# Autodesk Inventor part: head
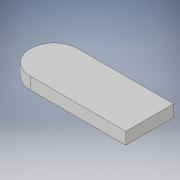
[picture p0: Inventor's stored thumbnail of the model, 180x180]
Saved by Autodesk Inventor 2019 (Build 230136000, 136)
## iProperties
Created: 2020-07
Part Number: head
Material: 一般
Document SubType Name: Modeling
Designer: kikut
Density: 1 g/cm^3
Appearance: 既定
Author: kikut
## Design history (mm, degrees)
sketch "スケッチ1"
  geometry: L1 (0.08, -0.02)-(0, -0.02); L2 (0, -0.02)-(0, 0.02); L3 (0, 0.02)-(0.08, 0.02); L4 (0.08, 0.02)-(0.08, -0.02); L5 (0.08, -0.02)-(0, 0.02); L6 (0, -0.02)-(0.08, 0.02); L7 (0.12, 0)-(-0.02, 0) reference; C1 r 0.02 at (0.08, 0); 2 further points
  constraints: 12 end point, 4 midpoint, 2 parallel, 1 centre point, 1 perpendicular
  dimensions: "d0" = 0.08 distance of L1.start L1.end; "d1" = 0.04 distance of L1.end L2.end; "d2" = 0 deg angle of L7 L1; "d3" = 0.02 distance from line of point (0, 0) L1; "d4" = 0.04 diameter of C1
extrude "押し出し1" new body sketch "スケッチ1" stored distance "d5" = 0.01; taper "d6" = 0 deg
node "ソリッド1"
